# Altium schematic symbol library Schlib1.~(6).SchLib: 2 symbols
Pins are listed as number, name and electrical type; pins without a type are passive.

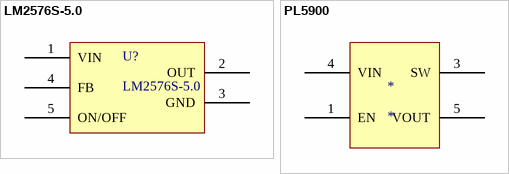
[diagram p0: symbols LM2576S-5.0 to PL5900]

## LM2576S-5.0
designator U?
footprint TO263-5A (263，5脚晶体管)
pins: 1 VIN, 2 OUT, 3 GND, 4 FB, 5 ON/OFF

## PL5900
designator *
footprint SOT23-5L (3x1.6x1.1mm(长宽高))
pins: 1 EN, 3 SW, 4 VIN, 5 VOUT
